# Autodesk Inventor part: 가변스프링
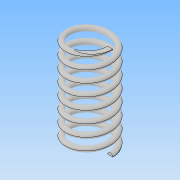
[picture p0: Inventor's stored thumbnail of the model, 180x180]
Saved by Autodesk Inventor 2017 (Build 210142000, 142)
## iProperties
Part Number: 가변스프링
Material: 일반
Document SubType Name: Modeling
Designer: user
Density: 1 g/cm^3
Appearance: 기본값
Author: user
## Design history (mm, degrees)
sketch "스케치1"
  geometry: L1 (0, 0)-(8, 0); L2 (8, 0)-(8, 37); L3 (8, 37)-(0, 37); L4 (0, 37)-(0, 0); C1 r 1 at (8, 0)
  constraints: 8 end point, 2 parallel, 1 centre point, 1 coincident, 1 horizontal, 1 perpendicular
  dimensions: "d1" = 37 distance of L2.end L1.end (derived); "d2" = 16 diameter of L2 L4; "d3" = 2 diameter of C1
feature "코일1" sketch "스케치1" pitch "d4" = 10; turns "d6" = 8; dims "d5" = 37 (= d1), "d7" = 0, angle "d8" = 90 deg, angle "d9" = 90 deg, "d10" = 0, "d11" = 0
node "작업 평면1"
sketch "스케치2"
  geometry: L1 (-9, 0)-(-7, 0) reference; L2 (-9, 0)-(-7, 0) reference; 1 further point
  constraints: 2 horizontal alignment
extrude "돌출1" cut sketch "스케치2" distance "d13" = 10; taper "d14" = 0 deg
node "작업 평면2"
sketch "스케치3"
  geometry: L1 (-7, 0)-(-9, 0) reference; 1 further point
  constraints: 1 horizontal alignment
extrude "돌출2" cut sketch "스케치3" distance "d16" = 10; taper "d17" = 0 deg
node "솔리드1"
node "절단 모서리 투영1"
node "절단 모서리 투영2"
node "절단 모서리 투영3"
other parameters: "d12" = 0, "d15" = 37 (= d1)
